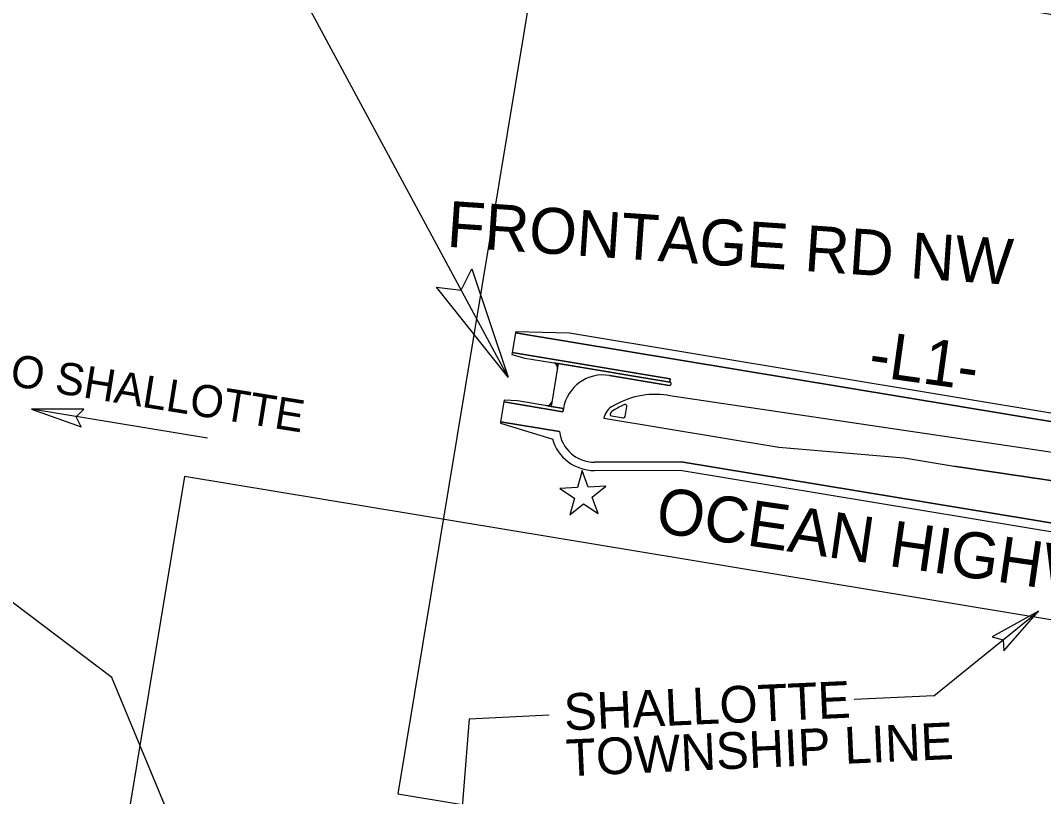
# Model space of a CAD drawing. Extents: x 2170913 to 2188101, y 74009 to 87693.
# Drawn here: x 2178181 to 2179407, y 78530 to 79461 of the extents above; entities that cross this region are included whole.
import ezdxf

# ---------------------------------------------------------------- set-up
doc = ezdxf.new("R2010")
doc.units = 0
for name, color, linetype in [('CTL Primary Horizontal and Vertical Cogo Elevation', 7, 'Continuous'), ('Exist Hydro Stream or Body of Water', 7, 'Continuous'), ('Exist Property Iron Pin CELL', 7, 'Continuous'), ('Exist Property Iron Pin Cogo Number', 7, 'Continuous'), ('Exist Right of Way Monument CELL', 7, 'Continuous'), ('Exist Structure Minor Pipes HDPE 30 Inch', 7, 'Continuous'), ('Exist Structure Minor Storm Sewer Manhole CELL', 7, 'Continuous'), ('Exist Utilities Water Fire Hydrant CELL', 7, 'Continuous')]:
    doc.layers.add(name, color=color, linetype=linetype)

msp = doc.modelspace()

# ---------------------------------------------------------------- linework, layer by layer
at = {"layer": 'CTL Primary Horizontal and Vertical Cogo Elevation'}
for p, q in [((2179275.9, 78651.2), (2179401.3, 78752.4)), ((2179275.9, 78651.2), (2179180.4, 78646.7)), ((2178719.3, 78623.7), (2178681.1, 78151)), ((2178719.3, 78623.7), (2178814.9, 78628.3))]:
    msp.add_line(p, q, dxfattribs=at)
at = {"layer": 'Exist Hydro Stream or Body of Water'}
msp.add_lwpolyline([(2178848.8, 78900.8), (2178827.8, 78899.8), (2178845.4, 78888.2), (2178839.8, 78867.9), (2178856.3, 78881.1), (2178873.9, 78869.5), (2178866.5, 78889.2), (2178882.9, 78902.4), (2178861.9, 78901.4), (2178854.4, 78921.1), (2178848.8, 78900.8)], dxfattribs=at)
at = {"layer": 'Exist Property Iron Pin CELL'}
for p, q in [((2178765.7, 79032.9), (2178309.2, 79881.2)), ((2178405.7, 78959.9), (2178194.8, 78994.7))]:
    msp.add_line(p, q, dxfattribs=at)
at = {"layer": 'Exist Property Iron Pin Cogo Number'}
for points in [[(2178257.6, 78994.8), (2178194.8, 78994.7), (2178254.3, 78973.4), (2178248.4, 78985.5)], [(2179359.8, 78705.2), (2179401.3, 78752.4), (2179345.9, 78721.9), (2179359, 78718.3)]]:
    msp.add_lwpolyline(points, close=True, dxfattribs=at)
at = {"layer": 'Exist Right of Way Monument CELL'}
for points in [[(2178805.2, 79569.3), (2178633.6, 78533.5), (2180113.4, 78288.3), (2180285.1, 79324.1)], [(2178378, 78914.1), (2178206.3, 77878.2), (2179686.1, 77633), (2179857.8, 78668.9)]]:
    msp.add_lwpolyline(points, close=True, dxfattribs=at)
at = {"layer": 'Exist Structure Minor Pipes HDPE 30 Inch'}
msp.add_lwpolyline([(2177668.6, 79896.6), (2182629.7, 80132.5), (2182882.8, 78325.4), (2178890.9, 77226), (2178290.9, 78673.1), (2177852.1, 79004.7), (2177687.9, 79128.8)], close=True, dxfattribs=at)
at = {"layer": 'Exist Structure Minor Storm Sewer Manhole CELL'}
msp.add_lwpolyline([(2178722.2, 79162.8), (2178765.7, 79032.9), (2178680.2, 79141.1), (2178709.5, 79137.3)], close=True, dxfattribs=at)
at = {"layer": 'Exist Utilities Water Fire Hydrant CELL'}
for p, q in [((2178774.7, 79087.5), (2178774.5, 79086.2)), ((2178839.3, 79085.6), (2178774.7, 79087.5)), ((2178774.5, 79086.2), (2178770.6, 79062.5)), ((2178774.5, 79086.2), (2179560.8, 78955.9)), ((2179560.8, 78955.9), (2178774.5, 79086.2)), ((2179562.4, 78965.8), (2178839.3, 79085.6)), ((2178770.6, 79062.5), (2178770.2, 79060.2)), ((2178960.2, 79031.1), (2178770.6, 79062.5)), ((2178770.6, 79062.5), (2178960.2, 79031.1)), ((2178770.2, 79060.2), (2178785.7, 79056)), ((2178785.7, 79056), (2178825.9, 79049.3)), ((2178825.9, 79049.3), (2178820, 79050.3)), ((2178825.9, 79049.3), (2178817.4, 78998)), ((2178824.9, 79043.4), (2178825.5, 79047.3)), ((2178825.5, 79047.3), (2178825.9, 79049.3)), ((2178959.5, 79027.2), (2178825.9, 79049.3)), ((2178825.9, 79049.3), (2178959.5, 79027.2)), ((2178887.4, 79035.1), (2178958.9, 79023.2)), ((2178958.9, 79023.2), (2178887.4, 79035.1)), ((2178959.5, 79027.2), (2178960.2, 79031.1)), ((2178960.2, 79031.1), (2178959.5, 79027.2)), ((2178760.8, 79003.3), (2178756.9, 78979.7)), ((2178761.1, 79005.3), (2178760.8, 79003.3)), ((2178760.8, 79003.3), (2178831.5, 78991.6)), ((2178831.5, 78991.6), (2178760.8, 79003.3)), ((2178777.2, 79004.7), (2178761.1, 79005.3)), ((2178817.4, 78998), (2178777.2, 79004.7)), ((2178817.7, 79000), (2178818.4, 79003.9)), ((2178957, 79011.4), (2179407.2, 78944.9)), ((2178811.5, 78999), (2178817.4, 78998)), ((2178817.4, 78998), (2178817.7, 79000)), ((2178817.4, 78998), (2178832.2, 78995.6)), ((2178832.2, 78995.6), (2178817.4, 78998)), ((2178831.5, 78991.6), (2178832.2, 78995.6)), ((2178832.2, 78995.6), (2178831.5, 78991.6)), ((2178906.2, 78986.1), (2178908.2, 78998)), ((2178756.9, 78979.7), (2178756.6, 78977.8)), ((2178756.6, 78977.8), (2178818.4, 78959.3)), ((2178827.3, 78968), (2178756.9, 78979.7)), ((2178756.9, 78979.7), (2178827.3, 78968)), ((2179090.3, 78948.7), (2178880.4, 78983.5)), ((2178889.6, 78986.8), (2178903.9, 78984.4)), ((2178818.4, 78959.3), (2178818.9, 78959.2)), ((2179240.3, 78936), (2179090.3, 78948.7)), ((2179407.2, 78944.9), (2179554.9, 78920.4)), ((2178973, 78931.7), (2178869.2, 78931.2)), ((2178869.2, 78931.2), (2178973, 78931.7)), ((2179541.2, 78837.5), (2178973, 78931.7)), ((2178973, 78931.7), (2179541.2, 78837.5)), ((2179300.4, 78926.1), (2179240.3, 78936)), ((2178869.2, 78921.2), (2178972.2, 78921.7)), ((2178972.2, 78921.7), (2179539.5, 78827.7))]:
    msp.add_line(p, q, dxfattribs=at)
for centre, radius, start, end in [((2178819, 79044.4), 6, 350.5917, 80.5917), ((2178879.5, 78987.7), 48, 80.5917, 170.5917), ((2178879.5, 78987.7), 48, 80.5917, 170.5917), ((2178959.2, 79025.2), 2, 260.5916, 80.5917), ((2178959.2, 79025.2), 2, 260.5916, 80.5917), ((2178812.4, 79004.9), 6, 260.5917, 350.5917), ((2178942.4, 78912.4), 100, 81.599, 121.874), ((2178900.2, 78980.4), 20, 121.8739, 170.9725), ((2178889.9, 78988.8), 2, 140.6312, 260.5917), ((2178900.2, 78980.4), 15.2, 121.8739, 140.6312), ((2178942.4, 78912.4), 95.2, 112.8573, 121.874), ((2178906.2, 78998.4), 2, 350.5917, 112.8573), ((2178904.2, 78986.4), 2, 260.5917, 350.5917), ((2178869, 78973.2), 42, 187.1932, 270.2406), ((2178869, 78973.2), 42, 187.1932, 270.2406), ((2178869, 78973.2), 52, 195.6207, 270.2406)]:
    msp.add_arc(centre, radius, start, end, dxfattribs=at)
for points in [[(2179321.8, 78922.9), (2179321.5, 78923), (2179321.3, 78923), (2179321.1, 78923), (2179320.8, 78923.1), (2179320.5, 78923.1), (2179320.2, 78923.2), (2179319.9, 78923.2), (2179319.7, 78923.2), (2179319.4, 78923.3), (2179319.1, 78923.3), (2179318.8, 78923.4), (2179318.5, 78923.4), (2179318.2, 78923.5), (2179317.9, 78923.5), (2179317.6, 78923.5), (2179317.3, 78923.6), (2179317, 78923.6), (2179316.8, 78923.7), (2179316.5, 78923.7), (2179316.2, 78923.8), (2179315.9, 78923.8), (2179315.6, 78923.8), (2179315.3, 78923.9), (2179315, 78923.9), (2179314.7, 78924), (2179314.4, 78924), (2179314.2, 78924.1), (2179313.9, 78924.1), (2179313.6, 78924.1), (2179313.3, 78924.2), (2179313, 78924.2), (2179312.7, 78924.3), (2179312.4, 78924.3), (2179312.1, 78924.4), (2179311.8, 78924.4), (2179311.5, 78924.4), (2179311.3, 78924.5), (2179311, 78924.5), (2179310.7, 78924.6), (2179310.4, 78924.6), (2179310.1, 78924.7), (2179309.8, 78924.7), (2179309.5, 78924.7), (2179309.2, 78924.8), (2179308.9, 78924.8), (2179308.6, 78924.9), (2179308.4, 78924.9), (2179308.1, 78925), (2179307.8, 78925), (2179307.5, 78925), (2179307.2, 78925.1), (2179306.9, 78925.1), (2179306.6, 78925.2), (2179306.3, 78925.2), (2179306, 78925.3), (2179305.8, 78925.3), (2179305.5, 78925.3), (2179305.2, 78925.4), (2179304.9, 78925.4), (2179304.6, 78925.5), (2179304.3, 78925.5), (2179304, 78925.6), (2179303.7, 78925.6), (2179303.4, 78925.6), (2179303.1, 78925.7), (2179302.9, 78925.7), (2179302.6, 78925.8), (2179302.3, 78925.8), (2179302, 78925.9), (2179301.7, 78925.9), (2179301.4, 78925.9), (2179301.1, 78926), (2179300.9, 78926), (2179300.6, 78926.1), (2179300.4, 78926.1)], [(2179343.2, 78919.8), (2179343, 78919.8), (2179342.9, 78919.8), (2179342.8, 78919.8), (2179342.5, 78919.9), (2179342.3, 78919.9), (2179342, 78919.9), (2179341.7, 78920), (2179341.4, 78920), (2179341.1, 78920.1), (2179340.8, 78920.1), (2179340.5, 78920.2), (2179340.2, 78920.2), (2179339.9, 78920.2), (2179339.6, 78920.3), (2179339.4, 78920.3), (2179339.1, 78920.4), (2179338.8, 78920.4), (2179338.5, 78920.5), (2179338.2, 78920.5), (2179337.9, 78920.5), (2179337.6, 78920.6), (2179337.3, 78920.6), (2179337, 78920.7), (2179336.7, 78920.7), (2179336.5, 78920.8), (2179336.2, 78920.8), (2179335.9, 78920.8), (2179335.6, 78920.9), (2179335.3, 78920.9), (2179335, 78921), (2179334.7, 78921), (2179334.4, 78921.1), (2179334.1, 78921.1), (2179333.9, 78921.1), (2179333.6, 78921.2), (2179333.3, 78921.2), (2179333, 78921.3), (2179332.7, 78921.3), (2179332.4, 78921.4), (2179332.1, 78921.4), (2179331.8, 78921.4), (2179331.5, 78921.5), (2179331.2, 78921.5), (2179331, 78921.6), (2179330.7, 78921.6), (2179330.4, 78921.7), (2179330.1, 78921.7), (2179329.8, 78921.7), (2179329.5, 78921.8), (2179329.2, 78921.8), (2179328.9, 78921.9), (2179328.6, 78921.9), (2179328.3, 78922), (2179328.1, 78922), (2179327.8, 78922), (2179327.5, 78922.1), (2179327.2, 78922.1), (2179326.9, 78922.2), (2179326.6, 78922.2), (2179326.3, 78922.3), (2179326, 78922.3), (2179325.7, 78922.3), (2179325.4, 78922.4), (2179325.2, 78922.4), (2179324.9, 78922.5), (2179324.6, 78922.5), (2179324.3, 78922.6), (2179324, 78922.6), (2179323.7, 78922.6), (2179323.4, 78922.7), (2179323.1, 78922.7), (2179322.8, 78922.8), (2179322.6, 78922.8), (2179322.3, 78922.9), (2179322, 78922.9), (2179321.9, 78922.9), (2179321.8, 78922.9), (2179321.8, 78922.9)], [(2179364.6, 78916.6), (2179364.3, 78916.7), (2179364, 78916.7), (2179363.7, 78916.7), (2179363.4, 78916.8), (2179363.1, 78916.8), (2179362.8, 78916.9), (2179362.5, 78916.9), (2179362.2, 78917), (2179362, 78917), (2179361.7, 78917), (2179361.4, 78917.1), (2179361.1, 78917.1), (2179360.8, 78917.2), (2179360.5, 78917.2), (2179360.2, 78917.3), (2179359.9, 78917.3), (2179359.6, 78917.3), (2179359.3, 78917.4), (2179359.1, 78917.4), (2179358.8, 78917.5), (2179358.5, 78917.5), (2179358.2, 78917.6), (2179357.9, 78917.6), (2179357.6, 78917.6), (2179357.3, 78917.7), (2179357, 78917.7), (2179356.7, 78917.8), (2179356.4, 78917.8), (2179356.2, 78917.9), (2179355.9, 78917.9), (2179355.6, 78917.9), (2179355.3, 78918), (2179355, 78918), (2179354.7, 78918.1), (2179354.4, 78918.1), (2179354.1, 78918.2), (2179353.8, 78918.2), (2179353.5, 78918.2), (2179353.3, 78918.3), (2179353, 78918.3), (2179352.7, 78918.4), (2179352.4, 78918.4), (2179352.1, 78918.5), (2179351.8, 78918.5), (2179351.5, 78918.5), (2179351.2, 78918.6), (2179350.9, 78918.6), (2179350.7, 78918.7), (2179350.4, 78918.7), (2179350.1, 78918.7), (2179349.8, 78918.8), (2179349.5, 78918.8), (2179349.2, 78918.9), (2179348.9, 78918.9), (2179348.6, 78919), (2179348.3, 78919), (2179348, 78919), (2179347.8, 78919.1), (2179347.5, 78919.1), (2179347.2, 78919.2), (2179346.9, 78919.2), (2179346.6, 78919.3), (2179346.3, 78919.3), (2179346, 78919.3), (2179345.7, 78919.4), (2179345.4, 78919.4), (2179345.1, 78919.5), (2179344.9, 78919.5), (2179344.6, 78919.6), (2179344.3, 78919.6), (2179344, 78919.6), (2179343.7, 78919.7), (2179343.5, 78919.7), (2179343.3, 78919.7), (2179343.2, 78919.8)]]:
    msp.add_open_spline(points, degree=3, dxfattribs=at)
for points in [[(2179386, 78913.4), (2179385.4, 78913.5), (2179384.5, 78913.7), (2179383.7, 78913.8), (2179382.8, 78913.9), (2179381.9, 78914), (2179381.1, 78914.2), (2179380.2, 78914.3), (2179379.3, 78914.4), (2179378.5, 78914.6), (2179377.6, 78914.7), (2179376.7, 78914.8), (2179375.9, 78914.9), (2179375, 78915.1), (2179374.1, 78915.2), (2179373.2, 78915.3), (2179372.4, 78915.5), (2179371.5, 78915.6), (2179370.6, 78915.7), (2179369.8, 78915.8), (2179368.9, 78916), (2179368, 78916.1), (2179367.2, 78916.2), (2179366.3, 78916.4), (2179365.4, 78916.5), (2179364.6, 78916.6)], [(2179407.4, 78910.3), (2179407.1, 78910.3), (2179406.3, 78910.4), (2179405.4, 78910.6), (2179404.5, 78910.7), (2179403.7, 78910.8), (2179402.8, 78911), (2179401.9, 78911.1), (2179401.1, 78911.2), (2179400.2, 78911.3), (2179399.3, 78911.5), (2179398.5, 78911.6), (2179397.6, 78911.7), (2179396.7, 78911.9), (2179395.8, 78912), (2179395, 78912.1), (2179394.1, 78912.2), (2179393.2, 78912.4), (2179392.4, 78912.5), (2179391.5, 78912.6), (2179390.6, 78912.8), (2179389.8, 78912.9), (2179388.9, 78913), (2179388, 78913.1), (2179387.2, 78913.3), (2179386.3, 78913.4), (2179386, 78913.4)], [(2179428.9, 78907.1), (2179428, 78907.2), (2179427.1, 78907.4), (2179426.3, 78907.5), (2179425.4, 78907.6), (2179424.5, 78907.8), (2179423.7, 78907.9), (2179422.8, 78908), (2179421.9, 78908.1), (2179421, 78908.3), (2179420.2, 78908.4), (2179419.3, 78908.5), (2179418.4, 78908.7), (2179417.6, 78908.8), (2179416.7, 78908.9), (2179415.8, 78909), (2179415, 78909.2), (2179414.1, 78909.3), (2179413.2, 78909.4), (2179412.4, 78909.6), (2179411.5, 78909.7), (2179410.6, 78909.8), (2179409.8, 78909.9), (2179408.9, 78910.1), (2179408, 78910.2), (2179407.4, 78910.3)]]:
    msp.add_spline(points, degree=3, dxfattribs=at)

# ---------------------------------------------------------------- texts
at = {"layer": 'Exist Property Iron Pin CELL'}
for s, height, rotation, p in [('FRONTAGE RD NW', 55.047, 356.1169, (2178691.5, 79189.5)), ('-L1-', 55.05, 352.037, (2179196.1, 79034.9)), ('TO SHALLOTTE', 38.533, 350.8535, (2178136.6, 79028.1)), ('OCEAN HIGHWAY W', 55.047, 351.7593, (2178941.1, 78847.4)), ('SHALLOTTE', 44.04, 2.5695, (2178833.6, 78609.6)), ('TOWNSHIP LINE', 44.037, 2.5695, (2178836.1, 78554.6))]:
    msp.add_text(s, height=height, rotation=rotation, dxfattribs=at).set_placement(p)

doc.saveas('drawing.dxf')
